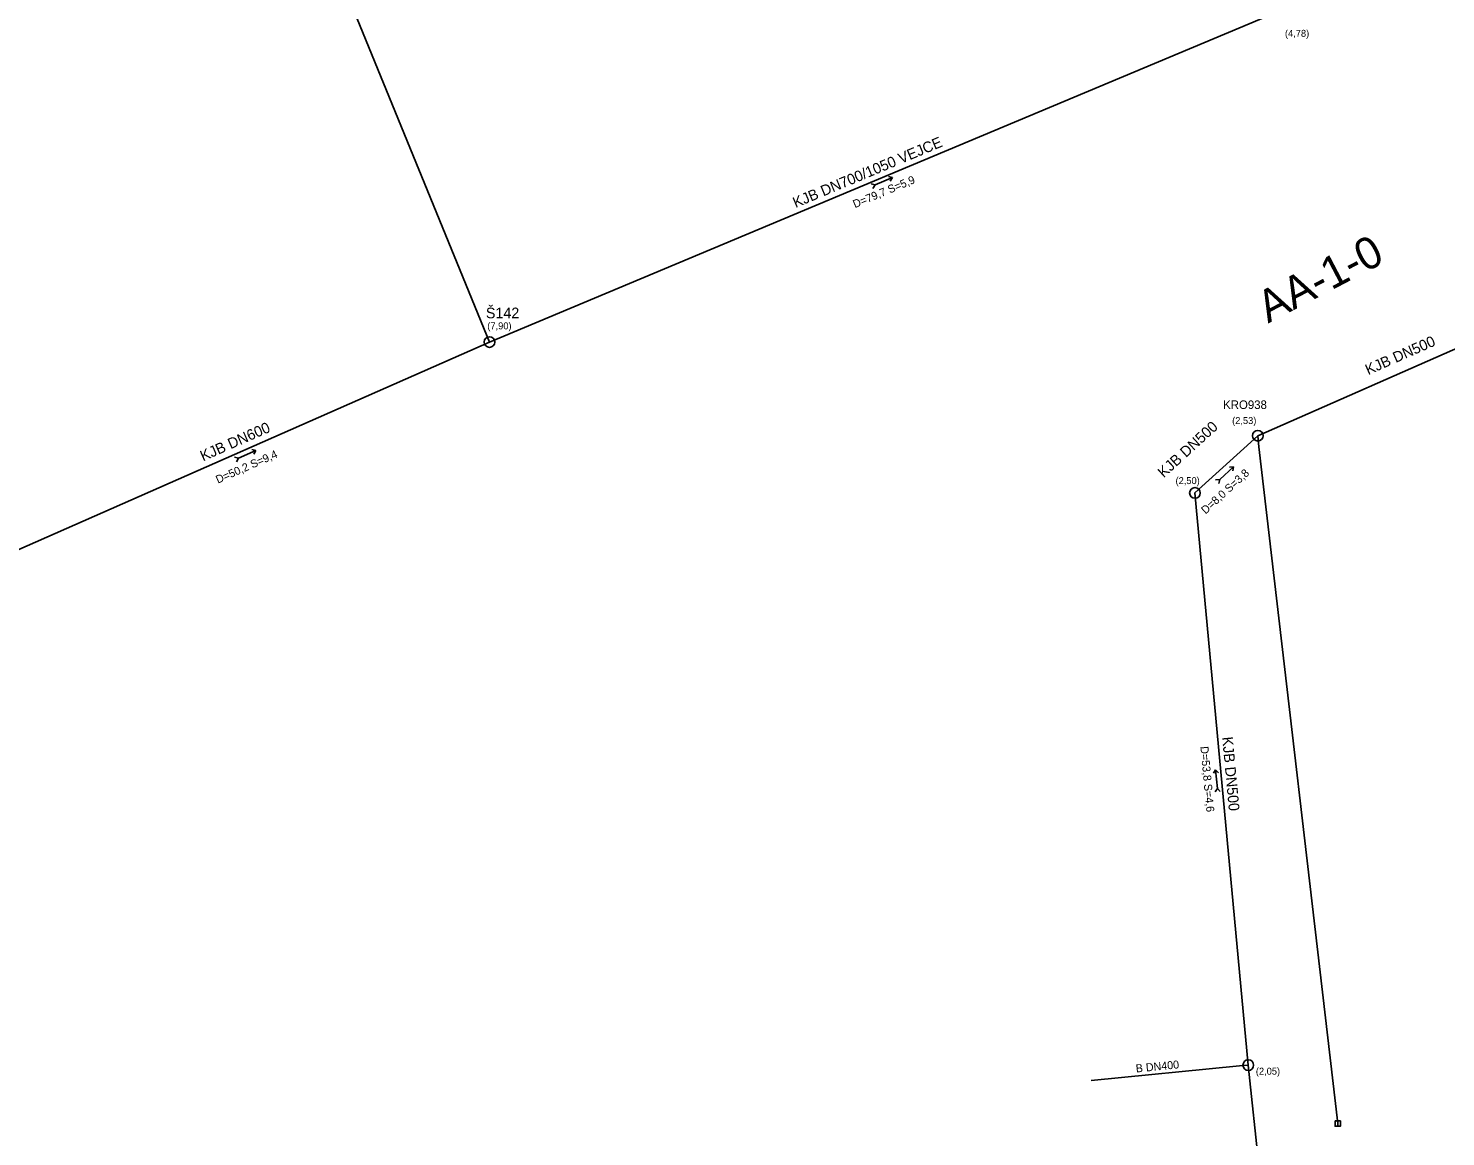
# Model space of a CAD drawing. Extents: x -539706 to -539225, y -1156458 to -1155912.
# Drawn here: x -539596.4 to -539463.7, y -1156127.6 to -1156023.7 of the extents above; entities that cross this region are included whole.
import ezdxf

# ---------------------------------------------------------------- set-up
doc = ezdxf.new("R2010")
doc.units = 0
for name, color, linetype in [('Vrstva 17', 7, 'Continuous'), ('Vrstva 29', 7, 'Continuous'), ('Vrstva 34', 7, 'Continuous'), ('Vrstva 39', 7, 'Continuous'), ('Vrstva 46', 7, 'Continuous'), ('Vrstva 52', 7, 'Continuous'), ('Vrstva 54', 7, 'Continuous'), ('Vrstva 57', 7, 'Continuous'), ('Vrstva 59', 7, 'Continuous'), ('Vrstva 60', 7, 'Continuous'), ('Vrstva 7', 7, 'Continuous'), ('Vrstva 9', 7, 'Continuous')]:
    doc.layers.add(name, color=color, linetype=linetype)

msp = doc.modelspace()

# ---------------------------------------------------------------- linework, layer by layer
at = {"layer": 'Vrstva 17'}
for p, q in [((-539481.168, -1156062.919), (-539481.25, -1156061.88)), ((-539473.757, -1156126.357), (-539481.168, -1156062.919)), ((-539496.86, -1156122.32), (-539482.972, -1156120.952)), ((-539482.972, -1156120.952), (-539482.14, -1156120.87))]:
    msp.add_line(p, q, dxfattribs=at)
at = {"layer": 'Vrstva 29'}
for centre in [(-539553.23, -1156053.1), (-539481.25, -1156061.88), (-539487.14, -1156067.25), (-539482.14, -1156120.87)]:
    msp.add_circle(centre, 0.5, dxfattribs=at)
at = {"layer": 'Vrstva 34'}
msp.add_line((-539473.757, -1156126.107), (-539473.757, -1156126.607), dxfattribs=at)
msp.add_lwpolyline([(-539474.008, -1156126.107), (-539474.007, -1156126.607), (-539473.507, -1156126.607), (-539473.507, -1156126.108)], close=True, dxfattribs=at)
at = {"layer": 'Vrstva 39'}
for p, q in [((-539517.108, -1156038.361), (-539515.489, -1156037.685)), ((-539515.863, -1156037.588), (-539515.489, -1156037.685)), ((-539515.684, -1156038.016), (-539515.489, -1156037.685)), ((-539517.488, -1156038.262), (-539517.108, -1156038.361)), ((-539517.304, -1156038.703), (-539517.108, -1156038.361)), ((-539577.127, -1156063.881), (-539576.745, -1156063.973)), ((-539576.935, -1156064.318), (-539576.745, -1156063.973)), ((-539576.745, -1156063.973), (-539575.14, -1156063.267)), ((-539575.515, -1156063.177), (-539575.14, -1156063.267)), ((-539575.328, -1156063.602), (-539575.14, -1156063.267)), ((-539484.823, -1156065.976), (-539483.526, -1156064.795)), ((-539483.91, -1156064.829), (-539483.526, -1156064.795)), ((-539483.598, -1156065.172), (-539483.526, -1156064.795)), ((-539485.214, -1156066.01), (-539484.823, -1156065.976)), ((-539484.894, -1156066.363), (-539484.823, -1156065.976)), ((-539485.406, -1156093.513), (-539485.201, -1156093.186)), ((-539485.04, -1156094.933), (-539485.201, -1156093.186)), ((-539484.944, -1156093.47), (-539485.201, -1156093.186)), ((-539485.248, -1156095.265), (-539485.04, -1156094.933)), ((-539484.773, -1156095.222), (-539485.04, -1156094.933))]:
    msp.add_line(p, q, dxfattribs=at)
at = {"layer": 'Vrstva 9'}
for p, q in [((-539595.06, -1155950.821), (-539553.23, -1156053.1)), ((-539553.23, -1156053.1), (-539479.76, -1156022.3)), ((-539481.25, -1156061.88), (-539448.15, -1156047.31)), ((-539599.2, -1156073.37), (-539553.23, -1156053.1)), ((-539487.14, -1156067.25), (-539481.25, -1156061.88)), ((-539482.14, -1156120.87), (-539487.14, -1156067.25)), ((-539479.78, -1156143.55), (-539482.14, -1156120.87))]:
    msp.add_line(p, q, dxfattribs=at)

# ---------------------------------------------------------------- texts
at = {"layer": 'Vrstva 46'}
msp.add_text('B DN400', height=0.75, rotation=5.62463, dxfattribs=at).set_placement((-539492.646, -1156121.565))
at = {"layer": 'Vrstva 52'}
msp.add_text('KRO938', height=0.8, dxfattribs=at).set_placement((-539484.5, -1156059.375))
at = {"layer": 'Vrstva 54'}
for s, rotation, p in [('D=79,7 S=5,9', 22.74434, (-539518.999, -1156040.56)), ('D=50,2 S=9,4', 23.79459, (-539578.683, -1156066.38)), ('D=8,0 S=3,8', 42.35589, (-539486.144, -1156069.272)), ('D=53,8 S=4,6', 275.32735, (-539486.632, -1156091.022))]:
    msp.add_text(s, height=0.75, rotation=rotation, dxfattribs=at).set_placement(p)
at = {"layer": 'Vrstva 57'}
msp.add_text('Š142', height=1, dxfattribs=at).set_placement((-539553.57, -1156050.877))
at = {"layer": 'Vrstva 59'}
for s, p in [('(4,78)', (-539478.706, -1156024.495)), ('(7,90)', (-539553.44, -1156051.911)), ('(2,53)', (-539483.657, -1156060.787)), ('(2,50)', (-539488.959, -1156066.417)), ('(2,05)', (-539481.433, -1156121.768))]:
    msp.add_text(s, height=0.65, dxfattribs=at).set_placement(p)
at = {"layer": 'Vrstva 60'}
msp.add_text('AA-1-0', height=3, rotation=27.65154, dxfattribs=at).set_placement((-539480.284, -1156051.373))
at = {"layer": 'Vrstva 7'}
for s, rotation, p in [('KJB DN700/1050 VEJCE', 22.74448, (-539524.557, -1156040.55)), ('KJB DN500', 23.75819, (-539470.912, -1156056.206)), ('KJB DN600', 23.79309, (-539580.075, -1156064.296)), ('KJB DN500 ', 42.35589, (-539490.07, -1156065.877)), ('KJB DN500', 275.32971, (-539484.598, -1156090.135))]:
    msp.add_text(s, height=1, rotation=rotation, dxfattribs=at).set_placement(p)

doc.saveas('drawing.dxf')
